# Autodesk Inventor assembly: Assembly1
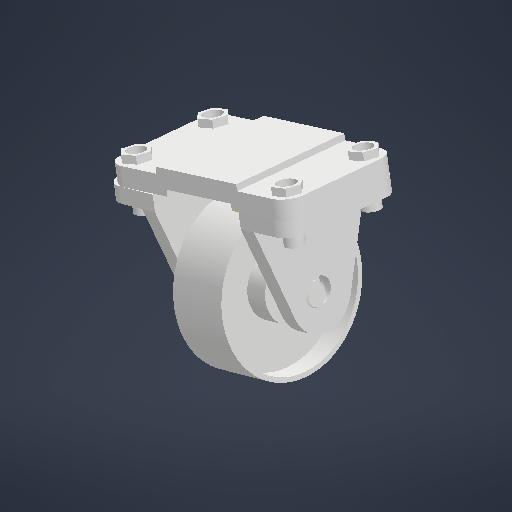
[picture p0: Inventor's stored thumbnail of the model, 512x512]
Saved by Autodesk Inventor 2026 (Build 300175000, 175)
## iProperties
Created: 2025-05
Part Number: Assembly1
Document SubType Name: Assembly
Designer: Ritul Kumari
Author: Ritul Kumari
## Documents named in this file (6)
- C:\Users\Ritul Kumari\Documents\Inventor\inventor P1\Assembly1.iam
- C:\Users\Ritul Kumari\Documents\Inventor\inventor P1\Part4.ipt
- C:\Users\Ritul Kumari\Documents\Inventor\inventor P1\Wheel.ipt
- C:\Users\Ritul Kumari\Documents\Inventor\inventor P1\axle support.ipt
- C:\Users\Ritul Kumari\Documents\Inventor\inventor P1\axle.ipt
- C:\Users\Ritul Kumari\Documents\Inventor\inventor P1\nut.ipt
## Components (9 placed, 5 different names)
1. Part4:1 — Insert:1, Insert:2, Insert:5, Insert:7, Insert:8, Insert:9
2. Wheel:1 — Insert:10
3. axle support:1 — Insert:2
4. axle support:2 — Insert:1
5. axle:1 — Insert:10
6. nut:2 — Insert:5
7. nut:4 — Insert:7
8. nut:5 — Insert:8
9. nut:6 — Insert:9
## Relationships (7: Insert 7)
- Insert:1: Part4:1 ↔ axle support:2
- Insert:2: Part4:1 ↔ axle support:1
- Insert:5: Part4:1 ↔ nut:2
- Insert:7: Part4:1 ↔ nut:4
- Insert:8: Part4:1 ↔ nut:5
- Insert:9: Part4:1 ↔ nut:6
- Insert:10: Wheel:1 ↔ axle:1
